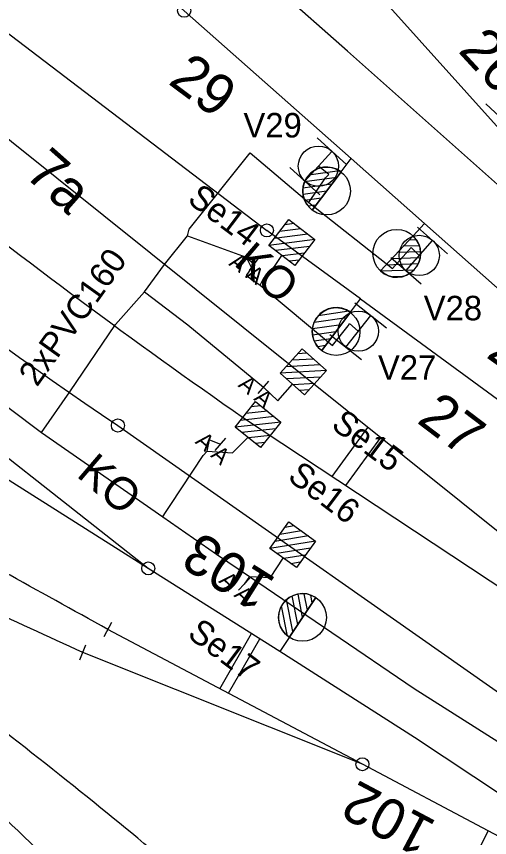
# Model space of a CAD drawing. Extents: x -496570 to -495506, y -1089156 to -1088046.
# Drawn here: x -496069.2 to -496040.3, y -1088592.2 to -1088542 of the extents above; entities that cross this region are included whole.
import ezdxf

# ---------------------------------------------------------------- set-up
doc = ezdxf.new("R2010")
doc.units = 0
for name, color, linetype in [('11', 7, 'Continuous'), ('14', 7, 'Continuous'), ('15', 7, 'Continuous'), ('20', 7, 'Continuous'), ('27', 7, 'Continuous'), ('54', 7, 'Continuous'), ('PŮVODNÍ_NÁVRH', 7, 'Continuous')]:
    doc.layers.add(name, color=color, linetype=linetype)

msp = doc.modelspace()

# ---------------------------------------------------------------- linework, layer by layer
at = {"layer": '11'}
for p, q in [((-496056.794, -1088583.079), (-496054.844, -1088579.712)), ((-496056.263, -1088583.36), (-496054.336, -1088580.033))]:
    msp.add_line(p, q, dxfattribs=at)
for points in [[(-496049.909, -1088570.098), (-496047.742, -1088567.112)], [(-496049.074, -1088570.652), (-496046.946, -1088567.719)]]:
    msp.add_lwpolyline(points, dxfattribs=at)
at = {"layer": '14'}
for p, q in [((-496075.335, -1088538.747), (-496053.911, -1088555.054)), ((-496044.26, -1088554.627), (-496048.752, -1088550.648)), ((-496048.18, -1088559.237), (-496053.911, -1088555.054)), ((-496055.342, -1088566.508), (-496037.913, -1088578.03))]:
    msp.add_line(p, q, dxfattribs=at)
for points in [[(-496036.118, -1088555.5), (-496048.975, -1088544.1), (-496066.196, -1088528.906), (-496086.152, -1088511.349), (-496104.929, -1088494.746), (-496123.588, -1088478.229), (-496142.293, -1088461.701), (-496160.965, -1088445.175), (-496179.891, -1088428.396), (-496198.214, -1088412.189), (-496217.292, -1088395.311), (-496245.811, -1088370.064), (-496264.918, -1088353.145), (-496281.988, -1088338.018), (-496302.247, -1088320.079), (-496322.57, -1088302.076), (-496341.966, -1088284.907), (-496360.552, -1088268.447), (-496378.713, -1088252.378), (-496398.4, -1088234.928), (-496416.447, -1088218.945), (-496437.668, -1088200.162), (-496456.103, -1088183.845), (-496474.042, -1088168.071)], [(-496075.31, -1088545), (-496052.489, -1088563.281), (-496031.561, -1088580.038)], [(-496061.169, -1088575.721), (-496076.075, -1088564.025)], [(-496035.857, -1088592.043), (-496044.874, -1088586.073), (-496053.125, -1088580.797), (-496061.169, -1088575.721), (-496076.529, -1088566.028)], [(-496063.029, -1088566.985), (-496037.138, -1088585.134), (-496023.296, -1088594.829), (-496003.341, -1088609.037)], [(-496037.513, -1088593.285), (-496040.369, -1088591.776), (-496048.068, -1088587.699), (-496063.641, -1088579.453)], [(-496048.068, -1088587.699), (-496065.173, -1088580.858)]]:
    msp.add_lwpolyline(points, dxfattribs=at)
for centre in [(-496053.911, -1088555.054), (-496063.029, -1088566.985)]:
    msp.add_circle(centre, 0.4, dxfattribs=at)
for centre, major_axis, ratio, start_param, end_param in [((-495832.376, -1088245.472), (-305.585, 244.796), 0.998266, 1.513638, 1.639034), ((-495921.531, -1088356.146), (-198.567, 158.721), 0.998858, 1.500529, 1.653958)]:
    msp.add_ellipse(centre, major_axis=major_axis, ratio=ratio, start_param=start_param, end_param=end_param, dxfattribs=at)
for points in [[(-496012.573, -1088566.09), (-496028.822, -1088547.857), (-496038.151, -1088535.934), (-496051.597, -1088517.251)], [(-496063.641, -1088579.453), (-496076.368, -1088572.308), (-496088.307, -1088565.016), (-496095.758, -1088560.128), (-496107.252, -1088552.116), (-496120.36, -1088541.773)], [(-496065.173, -1088580.858), (-496077.902, -1088574.814), (-496089.968, -1088568.076), (-496092.861, -1088566.414)], [(-496009.526, -1088642.986), (-496015.368, -1088636.526), (-496021.579, -1088629.917), (-496040.398, -1088611.545), (-496052.231, -1088600.497), (-496064.07, -1088590.377), (-496077.737, -1088579.829), (-496084.463, -1088574.911)], [(-496055.593, -1088604.743), (-496067.647, -1088593.203), (-496079.673, -1088581.848), (-496085.454, -1088576.574)]]:
    msp.add_spline(points, degree=3, dxfattribs=at)
at = {"layer": '15'}
for p, q in [((-496040.521, -1088547.306), (-496038.724, -1088548.991)), ((-496050.841, -1088549.39), (-496049.02, -1088551.049)), ((-496051.59, -1088552.041), (-496049.93, -1088550.219)), ((-496052.5, -1088551.211), (-496050.679, -1088552.87)), ((-496051.824, -1088554.961), (-496053.142, -1088555.129)), ((-496052.244, -1088554.637), (-496052.817, -1088554.71)), ((-496044.704, -1088554.851), (-496042.851, -1088556.476)), ((-496051.404, -1088555.286), (-496053.467, -1088555.549)), ((-496050.985, -1088555.61), (-496053.791, -1088555.968)), ((-496045.402, -1088557.516), (-496043.778, -1088555.664)), ((-496051.31, -1088556.029), (-496053.372, -1088556.292)), ((-496051.634, -1088556.449), (-496052.952, -1088556.617)), ((-496051.959, -1088556.868), (-496052.533, -1088556.942)), ((-496046.329, -1088556.704), (-496044.476, -1088558.329)), ((-496048.521, -1088559.489), (-496046.589, -1088561.019)), ((-496049.085, -1088562.186), (-496047.555, -1088560.254)), ((-496050.051, -1088561.421), (-496048.119, -1088562.951)), ((-496051.062, -1088562.919), (-496052.388, -1088562.992)), ((-496051.457, -1088562.566), (-496052.034, -1088562.598)), ((-496050.666, -1088563.273), (-496052.742, -1088563.388)), ((-496050.271, -1088563.627), (-496053.095, -1088563.783)), ((-496050.625, -1088564.022), (-496052.7, -1088564.137)), ((-496050.979, -1088564.417), (-496052.305, -1088564.491)), ((-496051.332, -1088564.812), (-496051.91, -1088564.844)), ((-496054.294, -1088565.778), (-496054.869, -1088565.843)), ((-496053.465, -1088566.44), (-496055.531, -1088566.672)), ((-496053.88, -1088566.109), (-496055.2, -1088566.257)), ((-496053.051, -1088566.771), (-496055.861, -1088567.086)), ((-496053.381, -1088567.185), (-496055.447, -1088567.417)), ((-496053.713, -1088567.6), (-496055.032, -1088567.748)), ((-496054.043, -1088568.014), (-496054.618, -1088568.079)), ((-496051.802, -1088573.431), (-496053.112, -1088573.645)), ((-496052.232, -1088573.121), (-496052.803, -1088573.214)), ((-496050.94, -1088574.05), (-496053.732, -1088574.506)), ((-496051.371, -1088573.741), (-496053.422, -1088574.076)), ((-496051.25, -1088574.481), (-496053.302, -1088574.816)), ((-496051.56, -1088574.912), (-496052.87, -1088575.126)), ((-496051.869, -1088575.342), (-496052.44, -1088575.435))]:
    msp.add_line(p, q, dxfattribs=at)
for points in [[(-496052.209, -1088557.192), (-496053.791, -1088555.968), (-496052.567, -1088554.386), (-496050.985, -1088555.61)], [(-496052.209, -1088557.192), (-496053.791, -1088555.968), (-496052.567, -1088554.386), (-496050.985, -1088555.61)], [(-496051.605, -1088565.117), (-496053.095, -1088563.783), (-496051.761, -1088562.293), (-496050.271, -1088563.627)], [(-496051.605, -1088565.117), (-496053.095, -1088563.783), (-496051.761, -1088562.293), (-496050.271, -1088563.627)], [(-496054.299, -1088568.334), (-496055.861, -1088567.086), (-496054.614, -1088565.523), (-496053.051, -1088566.771)], [(-496054.299, -1088568.334), (-496055.861, -1088567.086), (-496054.614, -1088565.523), (-496053.051, -1088566.771)], [(-496052.108, -1088575.674), (-496053.732, -1088574.506), (-496052.564, -1088572.882), (-496050.94, -1088574.05)], [(-496052.108, -1088575.674), (-496053.732, -1088574.506), (-496052.564, -1088572.882), (-496050.94, -1088574.05)]]:
    msp.add_lwpolyline(points, close=True, dxfattribs=at)
for points in [[(-496052.209, -1088557.192), (-496053.791, -1088555.968), (-496052.567, -1088554.386), (-496050.985, -1088555.61), (-496052.209, -1088557.192)], [(-496052.209, -1088557.192), (-496053.791, -1088555.968), (-496052.567, -1088554.386), (-496050.985, -1088555.61), (-496052.209, -1088557.192)], [(-496051.605, -1088565.117), (-496053.095, -1088563.783), (-496051.761, -1088562.293), (-496050.271, -1088563.627), (-496051.605, -1088565.117)], [(-496051.605, -1088565.117), (-496053.095, -1088563.783), (-496051.761, -1088562.293), (-496050.271, -1088563.627), (-496051.605, -1088565.117)], [(-496054.299, -1088568.334), (-496055.861, -1088567.086), (-496054.614, -1088565.523), (-496053.051, -1088566.771), (-496054.299, -1088568.334)], [(-496054.299, -1088568.334), (-496055.861, -1088567.086), (-496054.614, -1088565.523), (-496053.051, -1088566.771), (-496054.299, -1088568.334)], [(-496052.108, -1088575.674), (-496053.732, -1088574.506), (-496052.564, -1088572.882), (-496050.94, -1088574.05), (-496052.108, -1088575.674)], [(-496052.108, -1088575.674), (-496053.732, -1088574.506), (-496052.564, -1088572.882), (-496050.94, -1088574.05), (-496052.108, -1088575.674)]]:
    msp.add_lwpolyline(points, dxfattribs=at)
for centre in [(-496050.758, -1088551.126), (-496044.588, -1088556.585), (-496048.318, -1088561.215)]:
    msp.add_circle(centre, 1.232, dxfattribs=at)
at = {"layer": '20'}
for p, q in [((-496054.976, -1088557.513), (-496054.384, -1088556.707)), ((-496054.44, -1088565.028), (-496053.792, -1088564.266)), ((-496057.074, -1088568.511), (-496056.414, -1088567.759)), ((-496055.64, -1088577.057), (-496054.958, -1088576.325))]:
    msp.add_line(p, q, dxfattribs=at)
at = {"layer": '27'}
for p, q in [((-496049.369, -1088551.47), (-496048.752, -1088550.648)), ((-496049.465, -1088551.409), (-496051.345, -1088551.67)), ((-496051.135, -1088553.806), (-496049.371, -1088551.47)), ((-496049.37, -1088551.471), (-496051.135, -1088553.806)), ((-496049.371, -1088551.47), (-496049.37, -1088551.471)), ((-496049.626, -1088551.81), (-496051.605, -1088552.086)), ((-496049.946, -1088552.233), (-496051.705, -1088552.478)), ((-496050.267, -1088552.656), (-496051.697, -1088552.855)), ((-496050.586, -1088553.079), (-496051.592, -1088553.219)), ((-496050.906, -1088553.502), (-496051.378, -1088553.568)), ((-496044.959, -1088555.381), (-496044.26, -1088554.627)), ((-496046.963, -1088557.528), (-496044.967, -1088555.387)), ((-496046.956, -1088557.522), (-496044.96, -1088555.381)), ((-496044.582, -1088555.99), (-496045.562, -1088556.026)), ((-496044.764, -1088555.627), (-496045.205, -1088555.642)), ((-496044.508, -1088556.359), (-496045.919, -1088556.408)), ((-496044.528, -1088556.729), (-496046.276, -1088556.79)), ((-496044.926, -1088557.484), (-496046.932, -1088557.554)), ((-496044.652, -1088557.104), (-496046.633, -1088557.174)), ((-496046.963, -1088557.528), (-496046.963, -1088557.528)), ((-496045.624, -1088557.878), (-496046.214, -1088557.899)), ((-496048.794, -1088560.062), (-496048.18, -1088559.237)), ((-496048.889, -1088560.001), (-496050.769, -1088560.271)), ((-496049.049, -1088560.403), (-496051.027, -1088560.688)), ((-496050.549, -1088562.405), (-496048.795, -1088560.062)), ((-496048.794, -1088560.063), (-496050.549, -1088562.405)), ((-496048.795, -1088560.062), (-496048.794, -1088560.063)), ((-496049.366, -1088560.827), (-496051.124, -1088561.08)), ((-496049.685, -1088561.252), (-496051.114, -1088561.457)), ((-496050.003, -1088561.676), (-496051.008, -1088561.821)), ((-496050.321, -1088562.101), (-496050.793, -1088562.169)), ((-496050.922, -1088577.511), (-496052.551, -1088579.944)), ((-496052.55, -1088579.943), (-496050.922, -1088577.511)), ((-496052.019, -1088579.15), (-496052.365, -1088577.407)), ((-496051.724, -1088578.709), (-496052.005, -1088577.291)), ((-496051.43, -1088578.268), (-496051.627, -1088577.271)), ((-496051.135, -1088577.826), (-496051.227, -1088577.359)), ((-496052.64, -1088579.875), (-496053.009, -1088578.012)), ((-496052.314, -1088579.591), (-496052.702, -1088577.631)), ((-496063.875, -1088579.895), (-496063.407, -1088579.011)), ((-496052.551, -1088579.944), (-496053.125, -1088580.797)), ((-496052.551, -1088579.944), (-496052.55, -1088579.943)), ((-496065.359, -1088581.322), (-496064.987, -1088580.394)), ((-496040.828, -1088592.696), (-496040.369, -1088591.776))]:
    msp.add_line(p, q, dxfattribs=at)
for points in [[(-496048.752, -1088550.648), (-496058.972, -1088541.619), (-496073.961, -1088528.378)], [(-496038.935, -1088549.668), (-496047.32, -1088540.34), (-496055.467, -1088530.486)], [(-496019.1, -1088576.895), (-496034.077, -1088563.64), (-496044.26, -1088554.627)], [(-496048.18, -1088559.237), (-496037.202, -1088567.279), (-496021.082, -1088579.088)], [(-496061.169, -1088575.721), (-496076.075, -1088564.025)], [(-496053.125, -1088580.797), (-496061.169, -1088575.721), (-496076.529, -1088566.028)], [(-496040.369, -1088591.776), (-496048.068, -1088587.699), (-496063.641, -1088579.453)], [(-496048.068, -1088587.699), (-496065.173, -1088580.858)]]:
    msp.add_lwpolyline(points, dxfattribs=at)
for centre, radius in [((-496058.972, -1088541.619), 0.4), ((-496050.259, -1088552.644), 1.462), ((-496045.964, -1088556.457), 1.462), ((-496049.677, -1088561.24), 1.462), ((-496061.169, -1088575.721), 0.4), ((-496051.733, -1088578.72), 1.462), ((-496048.068, -1088587.699), 0.4)]:
    msp.add_circle(centre, radius, dxfattribs=at)
for centre, start, end in [((-496050.253, -1088552.638), 52.9473, 232.9081), ((-496045.965, -1088556.457), 227.0363, 46.9972), ((-496049.671, -1088561.234), 53.2096, 233.1704), ((-496051.736, -1088578.727), 56.2228, 236.1837)]:
    msp.add_arc(centre, 1.464, start, end, dxfattribs=at)
at = {"layer": '54'}
for p, q in [((-496055.17, -1088556.68), (-496054.68, -1088557.11)), ((-496054.978, -1088576.218), (-496055.299, -1088576.691))]:
    msp.add_line(p, q, dxfattribs=at)
for points in [[(-496165.07, -1088482.9), (-496156.87, -1088489.91), (-496145.17, -1088500.37), (-496132.17, -1088511.64), (-496132.14, -1088511.95), (-496109.93, -1088531.36), (-496085.16, -1088553.21), (-496080.73, -1088556.99), (-496073.59, -1088563.01), (-496067.7, -1088567.42), (-496060.271, -1088572.567), (-496056.99, -1088574.85), (-496054.978, -1088576.218), (-496044.9, -1088583.07), (-496037.32, -1088587.86), (-496035.7, -1088586.08), (-496034.22, -1088583.93), (-496031.57, -1088584.92), (-496029.17, -1088586.56)], [(-496067.7, -1088567.42), (-496065.97, -1088564.92), (-496063.17, -1088560.8), (-496061.41, -1088558.81), (-496060.18, -1088557.14), (-496058.77, -1088555.39), (-496058.66, -1088554.98), (-496054.93, -1088550.3), (-496051.35, -1088553.34), (-496046.22, -1088557.39), (-496045.09, -1088556.09), (-496044.59, -1088556.59)], [(-496051.35, -1088553.34), (-496050.33, -1088551.84), (-496050.13, -1088551.63), (-496050.76, -1088551.13)], [(-496058.77, -1088555.39), (-496055.17, -1088556.68), (-496054.85, -1088557.34), (-496055.18, -1088557.81), (-496054.32, -1088558.4), (-496049.9, -1088562.1), (-496048.94, -1088560.89), (-496048.86, -1088560.75), (-496048.32, -1088561.22)], [(-496054.32, -1088558.4), (-496054.1, -1088557.95), (-496053.87, -1088557.89), (-496053, -1088556.58)], [(-496061.41, -1088558.81), (-496058.74, -1088560.83), (-496054.116, -1088564.647), (-496053.24, -1088565.48), (-496052.35, -1088564.45)], [(-496060.271, -1088572.567), (-496060.15, -1088572.37), (-496059.78, -1088571.82), (-496057.82, -1088568.82), (-496057.57, -1088568.56), (-496056.01, -1088568.66), (-496055.08, -1088567.71)], [(-496057.57, -1088568.56), (-496057.43, -1088567.87), (-496056.744, -1088568.135)], [(-496054.978, -1088576.218), (-496053.7, -1088576.27), (-496052.92, -1088575.09)]]:
    msp.add_lwpolyline(points, dxfattribs=at)
at = {"layer": 'PŮVODNÍ_NÁVRH'}
msp.add_lwpolyline([(-496067.7, -1088567.42), (-496065.97, -1088564.92), (-496063.17, -1088560.8), (-496061.41, -1088558.81), (-496060.18, -1088557.14), (-496058.77, -1088555.39)], dxfattribs=at)

# ---------------------------------------------------------------- texts
at = {"layer": '14'}
for s, height, rotation, p in [('7a', 2.5, 318.4806, (-496068.824, -1088551.702)), ('KO', 2, 319.4182, (-496056.005, -1088557.131)), ('KO', 2, 319.4182, (-496065.63, -1088570.056))]:
    msp.add_text(s, height=height, rotation=rotation, dxfattribs=at).set_placement(p)
at = {"layer": '15'}
for s, p in [('V29', (-496055.345, -1088549.371)), ('V28', (-496044.312, -1088560.554)), ('V27', (-496047.113, -1088564.187))]:
    msp.add_text(s, height=1.5, dxfattribs=at).set_placement(p)
at = {"layer": '20'}
for s, height, rotation, p in [('Se14', 1.5, 323.0438, (-496058.846, -1088553.3)), ('  A A', 1, 323.7516, (-496056.889, -1088556.71)), ('  A A', 1, 319.6141, (-496056.29, -1088564.088)), ('Se15', 1.5, 323.0438, (-496050.05, -1088567.094)), ('  A A', 1, 318.7235, (-496058.909, -1088567.542)), ('Se16', 1.5, 323.0438, (-496052.712, -1088570.264)), ('  A A', 1, 317.0193, (-496057.445, -1088576.034)), ('Se17', 1.5, 323.0438, (-496058.846, -1088579.876))]:
    msp.add_text(s, height=height, rotation=rotation, dxfattribs=at).set_placement(p)
at = {"layer": '27'}
for s, rotation, p in [('26', 312.6217, (-496042.265, -1088544.097)), ('29', 323.282, (-496060.018, -1088546.044)), ('28', 324.4824, (-496040.562, -1088562.767)), ('27', 322.8359, (-496044.8, -1088566.769)), ('103', 147.7469, (-496053.258, -1088576.393)), ('102', 152.0966, (-496043.438, -1088591.242))]:
    msp.add_text(s, height=2.5, rotation=rotation, dxfattribs=at).set_placement(p)
at = {"layer": '54'}
msp.add_text('2xPVC160', height=1.5, rotation=54.507, dxfattribs=at).set_placement((-496067.982, -1088564.671))

doc.saveas('drawing.dxf')
